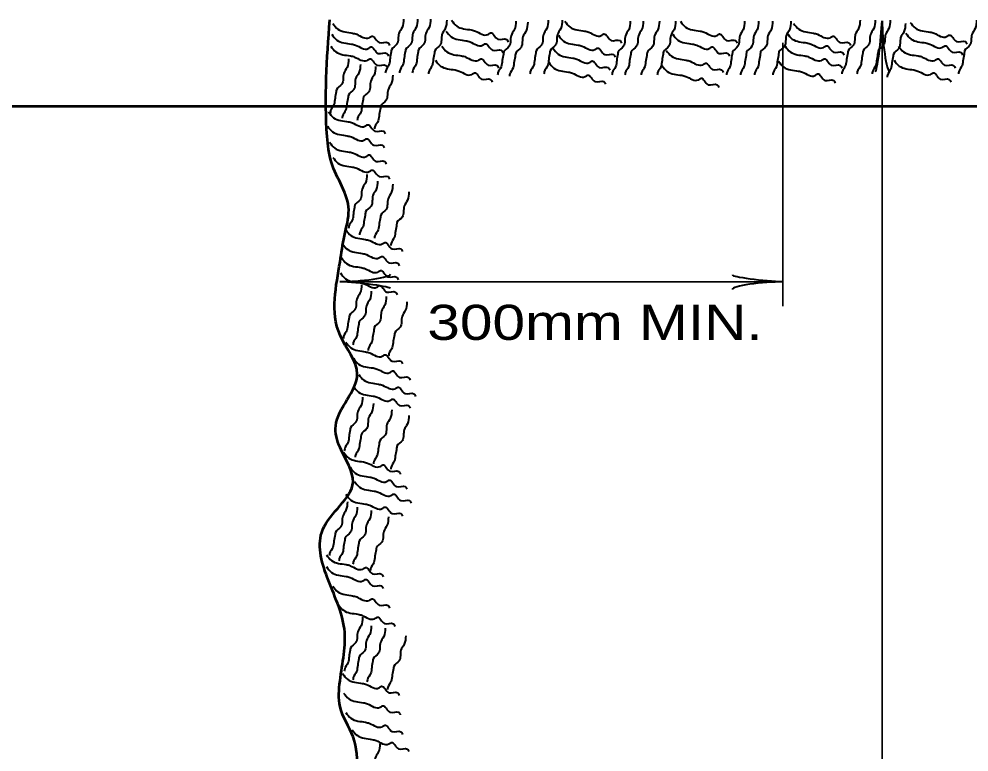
# Model space of a CAD drawing. Extents: x -617 to 238, y 23 to 567.
# Drawn here: x -228.6 to -163.5, y 332.5 to 382.7 of the extents above; entities that cross this region are included whole.
import ezdxf
from ezdxf.enums import TextEntityAlignment as Align

# ---------------------------------------------------------------- set-up
doc = ezdxf.new("R2010")
doc.units = 0
doc.header["$LTSCALE"] = 0.96
doc.layers.add('1', color=7, linetype='Continuous', lineweight=40)

msp = doc.modelspace()

# ---------------------------------------------------------------- linework, layer by layer
at = {"layer": '1', "lineweight": 35}
for p, q in [((-169.4809, 269.7739), (-169.4809, 382.5379)), ((-176.2772, 381.0289), (-176.2772, 363.0289)), ((-176.2772, 364.6978), (-206.5827, 364.6978))]:
    msp.add_line(p, q, dxfattribs=at)
at = {"layer": '1', "lineweight": 53}
msp.add_line((-325.834, 376.7054), (-133.834, 376.7054), dxfattribs=at)
at = {"layer": '1'}
for centre, major_axis, ratio, start_param, end_param in [((-169.7348, 381.1933), (-0.2108, -2.1077), 0.07063, 6.2823074, 8.5597026), ((-169.7348, 381.1933), (-0.2108, -2.1077), 0.07063, 6.2823074, 8.5597026), ((-169.1493, 381.2285), (-0.1874, 2.1428), 0.122415, 0.8963533, 3.1415927), ((-169.1493, 381.2285), (-0.1874, 2.1428), 0.122415, 0.8963533, 3.1415927), ((-205.2733, 365.0294), (-2.1428, -0.1874), 0.122415, 0.8963533, 3.1415927), ((-205.2733, 365.0294), (-2.1428, -0.1874), 0.122415, 0.8963533, 3.1415927), ((-177.6218, 364.9517), (2.1077, -0.2108), 0.07063, 3.1407148, 5.41811), ((-205.2381, 364.4439), (2.1077, -0.2108), 0.07063, 6.2823074, 8.5597026), ((-205.2381, 364.4439), (2.1077, -0.2108), 0.07063, 6.2823074, 8.5597026), ((-177.5866, 364.3662), (2.1428, 0.1874), 0.122415, 0.8963533, 3.1415927)]:
    msp.add_ellipse(centre, major_axis=major_axis, ratio=ratio, start_param=start_param, end_param=end_param, dxfattribs=at)
at = {"layer": '1', "lineweight": 53}
msp.add_spline([(-255.291, 382.6114), (-255.9281, 375.2243), (-254.7461, 372.2695), (-255.9281, 369.6102), (-255.0416, 367.2463), (-255.9281, 363.9961), (-254.7461, 361.9277), (-254.4506, 359.2684), (-254.7461, 355.1316), (-255.0416, 353.0633), (-256.2235, 351.5858), (-256.519, 350.6994), (-255.9281, 349.222), (-255.6326, 347.4491), (-255.3371, 345.3807), (-255.0416, 343.3124), (-255.0416, 340.9485), (-253.8597, 337.6982), (-254.1552, 335.6299), (-254.7461, 334.4479), (-254.7461, 331.1977), (-254.4506, 327.3564), (-254.7461, 325.879), (-254.7461, 322.6287), (-255.3371, 318.492), (-255.3371, 315.5372), (-256.519, 311.6959), (-255.6326, 309.6275), (-255.9281, 306.9682), (-256.2235, 303.7179), (-255.9281, 301.6495), (-255.6326, 298.1038), (-255.3371, 296.0354), (-255.6326, 293.6716), (-255.6326, 289.8303), (-254.7461, 288.9439), (-255.3371, 284.2162), (-255.3371, 281.5568), (-255.0416, 279.7839), (-255.6326, 276.2382), (-255.0416, 274.7608), (-255.6326, 272.1014), (-255.0416, 270.9195), (-252.6778, 268.5557), (-250.6094, 269.1466), (-248.541, 270.624), (-246.7681, 269.1466), (-244.9953, 268.8511), (-241.154, 268.8511), (-237.3127, 270.3286), (-236.1308, 269.4421), (-231.1076, 269.4421), (-226.6754, 270.0331), (-224.3116, 269.4421), (-219.2884, 270.0331), (-217.5155, 269.7376), (-212.1969, 270.0331), (-211.6059, 269.1466), (-208.0601, 269.7376), (-205.4008, 273.2834), (-205.6963, 275.3517), (-205.9918, 276.5337), (-207.7646, 282.1478), (-205.4008, 285.9891), (-206.8782, 289.2393), (-206.8782, 290.4213), (-205.6963, 292.4896), (-206.2872, 295.7399), (-205.4008, 297.2173), (-204.2189, 300.1721), (-205.9918, 305.1953), (-205.9918, 306.9682), (-205.6963, 309.0366), (-206.5827, 311.6959), (-206.2872, 313.4688), (-206.5827, 316.7191), (-207.7646, 320.8558), (-205.9918, 324.1061), (-205.6963, 326.7654), (-205.4008, 331.1977), (-205.6963, 333.5615), (-206.5827, 335.6299), (-206.5827, 337.4028), (-206.2872, 340.9485), (-207.4692, 344.4943), (-207.7646, 347.7446), (-205.6963, 350.9949), (-206.5827, 353.3587), (-206.8782, 354.8361), (-205.4008, 358.3819), (-206.5827, 361.0412), (-206.5827, 366.0644), (-206.2872, 367.8373), (-205.9918, 369.6102), (-207.1737, 372.8605), (-207.4692, 374.6334), (-207.291, 382.6114)], degree=3, dxfattribs=at)
at = {"layer": '1'}
for points in [[(-207.0771, 382.3659), (-206.7256, 381.9656), (-205.7266, 381.698), (-205.4412, 381.6216), (-204.585, 381.3921), (-204.404, 381.4966), (-203.9095, 381.0583), (-203.3006, 381.0479), (-203.1961, 380.8671)], [(-202.2362, 382.6687), (-202.3388, 382.0868), (-202.5612, 381.676), (-202.6895, 380.9484), (-203.0576, 380.5633), (-203.0831, 380.4179), (-203.1601, 379.9813), (-203.237, 379.5448), (-203.4596, 379.1341), (-203.4853, 378.9885)], [(-201.2759, 382.6687), (-201.3785, 382.0868), (-201.6009, 381.676), (-201.7292, 380.9484), (-202.0973, 380.5633), (-202.1228, 380.4179), (-202.1998, 379.9813), (-202.2767, 379.5448), (-202.4993, 379.1341), (-202.525, 378.9885)], [(-200.3895, 382.6687), (-200.4921, 382.0868), (-200.7145, 381.676), (-200.8428, 380.9484), (-201.2109, 380.5633), (-201.2364, 380.4179), (-201.3134, 379.9813), (-201.3903, 379.5448), (-201.6129, 379.1341), (-201.6386, 378.9885)], [(-199.2814, 382.5948), (-199.384, 382.0129), (-199.6064, 381.6021), (-199.7347, 380.8745), (-200.1028, 380.4894), (-200.1283, 380.344), (-200.2053, 379.9074), (-200.2822, 379.4709), (-200.5048, 379.0602), (-200.5305, 378.9146)], [(-198.9514, 382.5875), (-198.5999, 382.1872), (-197.6009, 381.9196), (-197.3155, 381.8432), (-196.4593, 381.6137), (-196.2783, 381.7182), (-195.7838, 381.2799), (-195.1749, 381.2695), (-195.0704, 381.0887)], [(-194.5537, 382.5209), (-194.6563, 381.939), (-194.8787, 381.5282), (-195.007, 380.8006), (-195.3751, 380.4155), (-195.4006, 380.2701), (-195.4776, 379.8335), (-195.5545, 379.397), (-195.7771, 378.9863), (-195.8028, 378.8407)], [(-193.7411, 382.4471), (-193.8437, 381.8652), (-194.0661, 381.4544), (-194.1944, 380.7268), (-194.5625, 380.3417), (-194.588, 380.1963), (-194.665, 379.7597), (-194.7419, 379.3232), (-194.9645, 378.9125), (-194.9902, 378.7669)], [(-192.3376, 382.5948), (-192.4402, 382.0129), (-192.6626, 381.6021), (-192.7909, 380.8745), (-193.159, 380.4894), (-193.1845, 380.344), (-193.2615, 379.9074), (-193.3384, 379.4709), (-193.561, 379.0602), (-193.5867, 378.9146)], [(-191.3772, 382.5948), (-191.4798, 382.0129), (-191.7022, 381.6021), (-191.8305, 380.8745), (-192.1986, 380.4894), (-192.2241, 380.344), (-192.3011, 379.9074), (-192.378, 379.4709), (-192.6006, 379.0602), (-192.6263, 378.9146)], [(-191.1949, 382.5137), (-190.8434, 382.1134), (-189.8444, 381.8458), (-189.559, 381.7694), (-188.7028, 381.5399), (-188.5218, 381.6444), (-188.0273, 381.2061), (-187.4184, 381.1957), (-187.3139, 381.0149)], [(-186.7234, 382.5209), (-186.826, 381.939), (-187.0484, 381.5282), (-187.1767, 380.8006), (-187.5448, 380.4155), (-187.5703, 380.2701), (-187.6473, 379.8335), (-187.7242, 379.397), (-187.9468, 378.9863), (-187.9725, 378.8407)], [(-185.837, 382.5209), (-185.9396, 381.939), (-186.162, 381.5282), (-186.2903, 380.8006), (-186.6584, 380.4155), (-186.6839, 380.2701), (-186.7609, 379.8335), (-186.8378, 379.397), (-187.0604, 378.9863), (-187.0861, 378.8407)], [(-184.7289, 382.5209), (-184.8315, 381.939), (-185.0539, 381.5282), (-185.1822, 380.8006), (-185.5503, 380.4155), (-185.5758, 380.2701), (-185.6528, 379.8335), (-185.7297, 379.397), (-185.9523, 378.9863), (-185.978, 378.8407)], [(-183.6209, 382.5209), (-183.7235, 381.939), (-183.9459, 381.5282), (-184.0742, 380.8006), (-184.4423, 380.4155), (-184.4678, 380.2701), (-184.5448, 379.8335), (-184.6217, 379.397), (-184.8443, 378.9863), (-184.87, 378.8407)], [(-183.2908, 382.5137), (-182.9393, 382.1134), (-181.9403, 381.8458), (-181.6549, 381.7694), (-180.7987, 381.5399), (-180.6177, 381.6444), (-180.1232, 381.2061), (-179.5143, 381.1957), (-179.4098, 381.0149)], [(-178.8932, 382.521), (-178.9958, 381.9391), (-179.2182, 381.5283), (-179.3465, 380.8007), (-179.7146, 380.4156), (-179.7401, 380.2702), (-179.8171, 379.8336), (-179.894, 379.3971), (-180.1166, 378.9864), (-180.1423, 378.8408)], [(-177.9329, 382.521), (-178.0355, 381.9391), (-178.2579, 381.5283), (-178.3862, 380.8007), (-178.7543, 380.4156), (-178.7798, 380.2702), (-178.8568, 379.8336), (-178.9337, 379.3971), (-179.1563, 378.9864), (-179.182, 378.8408)], [(-176.9726, 382.521), (-177.0752, 381.9391), (-177.2976, 381.5283), (-177.4259, 380.8007), (-177.794, 380.4156), (-177.8195, 380.2702), (-177.8965, 379.8336), (-177.9734, 379.3971), (-178.196, 378.9864), (-178.2217, 378.8408)], [(-175.7168, 382.521), (-175.8194, 381.9391), (-176.0418, 381.5283), (-176.1701, 380.8007), (-176.5382, 380.4156), (-176.5637, 380.2702), (-176.6407, 379.8336), (-176.7176, 379.3971), (-176.9402, 378.9864), (-176.9659, 378.8408)], [(-175.5345, 382.366), (-175.183, 381.9657), (-174.184, 381.6981), (-173.8986, 381.6217), (-173.0424, 381.3922), (-172.8614, 381.4967), (-172.3669, 381.0584), (-171.758, 381.048), (-171.6535, 380.8672)], [(-170.9891, 382.5948), (-171.0917, 382.0129), (-171.3141, 381.6021), (-171.4424, 380.8745), (-171.8105, 380.4894), (-171.836, 380.344), (-171.913, 379.9074), (-171.9899, 379.4709), (-172.2125, 379.0602), (-172.2382, 378.9146)], [(-169.9549, 382.5948), (-170.0575, 382.0129), (-170.2799, 381.6021), (-170.4082, 380.8745), (-170.7763, 380.4894), (-170.8018, 380.344), (-170.8788, 379.9074), (-170.9557, 379.4709), (-171.1783, 379.0602), (-171.204, 378.9146)], [(-168.9207, 382.5948), (-169.0233, 382.0129), (-169.2457, 381.6021), (-169.374, 380.8745), (-169.7421, 380.4894), (-169.7676, 380.344), (-169.8446, 379.9074), (-169.9215, 379.4709), (-170.1441, 379.0602), (-170.1698, 378.9146)], [(-167.8865, 382.3732), (-167.9891, 381.7913), (-168.2115, 381.3805), (-168.3398, 380.6529), (-168.7079, 380.2678), (-168.7334, 380.1224), (-168.8104, 379.6858), (-168.8873, 379.2493), (-169.1099, 378.8386), (-169.1356, 378.693)], [(-167.5565, 382.4397), (-167.205, 382.0394), (-166.206, 381.7718), (-165.9206, 381.6954), (-165.0644, 381.4659), (-164.8834, 381.5704), (-164.3889, 381.1321), (-163.78, 381.1217), (-163.6755, 380.9409)], [(-163.0111, 382.5948), (-163.1137, 382.0129), (-163.3361, 381.6021), (-163.4644, 380.8745), (-163.8325, 380.4894), (-163.858, 380.344), (-163.935, 379.9074), (-164.0119, 379.4709), (-164.2345, 379.0602), (-164.2602, 378.9146)], [(-199.3208, 381.8488), (-198.9693, 381.4485), (-197.9703, 381.1809), (-197.6849, 381.1045), (-196.8287, 380.875), (-196.6477, 380.9795), (-196.1532, 380.5412), (-195.5443, 380.5308), (-195.4398, 380.35)], [(-207.151, 381.6272), (-206.7995, 381.2269), (-205.8005, 380.9593), (-205.5151, 380.8829), (-204.6589, 380.6534), (-204.4779, 380.7579), (-203.9834, 380.3196), (-203.3745, 380.3092), (-203.27, 380.1284)], [(-191.6382, 381.5534), (-191.2867, 381.1531), (-190.2877, 380.8855), (-190.0023, 380.8091), (-189.1461, 380.5796), (-188.9651, 380.6841), (-188.4706, 380.2458), (-187.8617, 380.2354), (-187.7572, 380.0546)], [(-183.8079, 381.6272), (-183.4564, 381.2269), (-182.4574, 380.9593), (-182.172, 380.8829), (-181.3158, 380.6534), (-181.1348, 380.7579), (-180.6403, 380.3196), (-180.0314, 380.3092), (-179.9269, 380.1284)], [(-175.9777, 381.7011), (-175.6262, 381.3008), (-174.6272, 381.0332), (-174.3418, 380.9568), (-173.4856, 380.7273), (-173.3046, 380.8318), (-172.8101, 380.3935), (-172.2012, 380.3831), (-172.0967, 380.2023)], [(-167.8519, 381.701), (-167.5004, 381.3007), (-166.5014, 381.0331), (-166.216, 380.9567), (-165.3598, 380.7272), (-165.1788, 380.8317), (-164.6843, 380.3934), (-164.0754, 380.383), (-163.9709, 380.2022)], [(-207.2248, 380.8146), (-206.8733, 380.4143), (-205.8743, 380.1467), (-205.5889, 380.0703), (-204.7327, 379.8408), (-204.5517, 379.9453), (-204.0572, 379.507), (-203.4483, 379.4966), (-203.3438, 379.3158)], [(-199.6162, 380.8146), (-199.2647, 380.4143), (-198.2657, 380.1467), (-197.9803, 380.0703), (-197.1241, 379.8408), (-196.9431, 379.9453), (-196.4486, 379.507), (-195.8397, 379.4966), (-195.7352, 379.3158)], [(-192.0075, 380.6669), (-191.656, 380.2666), (-190.657, 379.999), (-190.3716, 379.9226), (-189.5154, 379.6931), (-189.3344, 379.7976), (-188.8399, 379.3593), (-188.231, 379.3489), (-188.1265, 379.1681)], [(-184.2511, 380.5192), (-183.8996, 380.1189), (-182.9006, 379.8513), (-182.6152, 379.7749), (-181.759, 379.5454), (-181.578, 379.6499), (-181.0835, 379.2116), (-180.4746, 379.2012), (-180.3701, 379.0204)], [(-176.1254, 380.8147), (-175.7739, 380.4144), (-174.7749, 380.1468), (-174.4895, 380.0704), (-173.6333, 379.8409), (-173.4523, 379.9454), (-172.9578, 379.5071), (-172.3489, 379.4967), (-172.2444, 379.3159)], [(-168.369, 380.8146), (-168.0175, 380.4143), (-167.0185, 380.1467), (-166.7331, 380.0703), (-165.8769, 379.8408), (-165.6959, 379.9453), (-165.2014, 379.507), (-164.5925, 379.4966), (-164.488, 379.3158)], [(-206.0036, 379.9355), (-206.1062, 379.3536), (-206.3286, 378.9428), (-206.4569, 378.2152), (-206.825, 377.8301), (-206.8505, 377.6847), (-206.9275, 377.2481), (-207.0044, 376.8116), (-207.227, 376.4009), (-207.2527, 376.2553)], [(-200.0595, 379.8543), (-199.708, 379.454), (-198.709, 379.1864), (-198.4236, 379.11), (-197.5674, 378.8805), (-197.3864, 378.985), (-196.8919, 378.5467), (-196.283, 378.5363), (-196.1785, 378.3555)], [(-176.5687, 379.7805), (-176.2172, 379.3802), (-175.2182, 379.1126), (-174.9328, 379.0362), (-174.0766, 378.8067), (-173.8956, 378.9112), (-173.4011, 378.4729), (-172.7922, 378.4625), (-172.6877, 378.2817)], [(-168.6645, 379.8543), (-168.313, 379.454), (-167.314, 379.1864), (-167.0286, 379.11), (-166.1724, 378.8805), (-165.9914, 378.985), (-165.4969, 378.5467), (-164.888, 378.5363), (-164.7835, 378.3555)], [(-205.1911, 379.5661), (-205.2937, 378.9842), (-205.5161, 378.5734), (-205.6444, 377.8458), (-206.0125, 377.4607), (-206.038, 377.3153), (-206.115, 376.8787), (-206.1919, 376.4422), (-206.4145, 376.0315), (-206.4402, 375.8859)], [(-204.1569, 379.4184), (-204.2595, 378.8365), (-204.4819, 378.4257), (-204.6102, 377.6981), (-204.9783, 377.313), (-205.0038, 377.1676), (-205.0808, 376.731), (-205.1577, 376.2945), (-205.3803, 375.8838), (-205.406, 375.7382)], [(-192.303, 379.7066), (-191.9515, 379.3063), (-190.9525, 379.0387), (-190.6671, 378.9623), (-189.8109, 378.7328), (-189.6299, 378.8373), (-189.1354, 378.399), (-188.5265, 378.3886), (-188.422, 378.2078)], [(-184.5466, 379.485), (-184.1951, 379.0847), (-183.1961, 378.8171), (-182.9107, 378.7407), (-182.0545, 378.5112), (-181.8735, 378.6157), (-181.379, 378.1774), (-180.7701, 378.167), (-180.6656, 377.9862)], [(-202.975, 378.8274), (-203.0776, 378.2455), (-203.3, 377.8347), (-203.4283, 377.1071), (-203.7964, 376.722), (-203.8219, 376.5766), (-203.8989, 376.14), (-203.9758, 375.7035), (-204.1984, 375.2928), (-204.2241, 375.1472)], [(-207.3726, 376.3086), (-207.0211, 375.9083), (-206.0221, 375.6407), (-205.7367, 375.5643), (-204.8805, 375.3348), (-204.6995, 375.4393), (-204.205, 375.001), (-203.5961, 374.9906), (-203.4916, 374.8098)], [(-207.4464, 375.3483), (-207.0949, 374.948), (-206.0959, 374.6804), (-205.8105, 374.604), (-204.9543, 374.3745), (-204.7733, 374.479), (-204.2788, 374.0407), (-203.6699, 374.0303), (-203.5654, 373.8495)], [(-207.2987, 374.2402), (-206.9472, 373.8399), (-205.9482, 373.5723), (-205.6628, 373.4959), (-204.8066, 373.2664), (-204.6256, 373.3709), (-204.1311, 372.9326), (-203.5222, 372.9222), (-203.4177, 372.7414)], [(-207.0771, 373.206), (-206.7256, 372.8057), (-205.7266, 372.5381), (-205.4412, 372.4617), (-204.585, 372.2322), (-204.404, 372.3367), (-203.9095, 371.8984), (-203.3006, 371.888), (-203.1961, 371.7072)], [(-204.7479, 372.0313), (-204.8505, 371.4494), (-205.0729, 371.0386), (-205.2012, 370.311), (-205.5693, 369.9259), (-205.5948, 369.7805), (-205.6718, 369.3439), (-205.7487, 368.9074), (-205.9713, 368.4967), (-205.997, 368.3511)], [(-204.0091, 371.5881), (-204.1117, 371.0062), (-204.3341, 370.5954), (-204.4624, 369.8678), (-204.8305, 369.4827), (-204.856, 369.3373), (-204.933, 368.9007), (-205.0099, 368.4642), (-205.2325, 368.0535), (-205.2582, 367.9079)], [(-202.975, 371.3665), (-203.0776, 370.7846), (-203.3, 370.3738), (-203.4283, 369.6462), (-203.7964, 369.2611), (-203.8219, 369.1157), (-203.8989, 368.6791), (-203.9758, 368.2426), (-204.1984, 367.8319), (-204.2241, 367.6863)], [(-201.8669, 370.8494), (-201.9695, 370.2675), (-202.1919, 369.8567), (-202.3202, 369.1291), (-202.6883, 368.744), (-202.7138, 368.5986), (-202.7908, 368.162), (-202.8677, 367.7255), (-203.0903, 367.3148), (-203.116, 367.1692)], [(-206.1907, 368.2567), (-205.8392, 367.8564), (-204.8402, 367.5888), (-204.5548, 367.5124), (-203.6986, 367.2829), (-203.5176, 367.3874), (-203.0231, 366.9491), (-202.4142, 366.9387), (-202.3097, 366.7579)], [(-206.4123, 367.2963), (-206.0608, 366.896), (-205.0618, 366.6284), (-204.7764, 366.552), (-203.9202, 366.3225), (-203.7392, 366.427), (-203.2447, 365.9887), (-202.6358, 365.9783), (-202.5313, 365.7975)], [(-206.4862, 366.336), (-206.1347, 365.9357), (-205.1357, 365.6681), (-204.8503, 365.5917), (-203.9941, 365.3622), (-203.8131, 365.4667), (-203.3186, 365.0284), (-202.7097, 365.018), (-202.6052, 364.8372)], [(-206.56, 365.3018), (-206.2085, 364.9015), (-205.2095, 364.6339), (-204.9241, 364.5575), (-204.0679, 364.328), (-203.8869, 364.4325), (-203.3924, 363.9942), (-202.7835, 363.9838), (-202.679, 363.803)], [(-205.1172, 364.4966), (-205.2198, 363.9147), (-205.4422, 363.5039), (-205.5705, 362.7763), (-205.9386, 362.3912), (-205.9641, 362.2458), (-206.0411, 361.8092), (-206.118, 361.3727), (-206.3406, 360.962), (-206.3663, 360.8164)], [(-204.4524, 364.0534), (-204.555, 363.4715), (-204.7774, 363.0607), (-204.9057, 362.3331), (-205.2738, 361.948), (-205.2993, 361.8026), (-205.3763, 361.366), (-205.4532, 360.9295), (-205.6758, 360.5188), (-205.7015, 360.3732)], [(-203.4182, 363.684), (-203.5208, 363.1021), (-203.7432, 362.6913), (-203.8715, 361.9637), (-204.2396, 361.5786), (-204.2651, 361.4332), (-204.3421, 360.9966), (-204.419, 360.5601), (-204.6416, 360.1494), (-204.6673, 360.0038)], [(-202.0146, 363.3147), (-202.1172, 362.7328), (-202.3396, 362.322), (-202.4679, 361.5944), (-202.836, 361.2093), (-202.8615, 361.0639), (-202.9385, 360.6273), (-203.0154, 360.1908), (-203.238, 359.7801), (-203.2637, 359.6345)], [(-206.1906, 360.5741), (-205.8391, 360.1738), (-204.8401, 359.9062), (-204.5547, 359.8298), (-203.6985, 359.6003), (-203.5175, 359.7048), (-203.023, 359.2665), (-202.4141, 359.2561), (-202.3096, 359.0753)], [(-205.6735, 359.4661), (-205.322, 359.0658), (-204.323, 358.7982), (-204.0376, 358.7218), (-203.1814, 358.4923), (-203.0004, 358.5968), (-202.5059, 358.1585), (-201.897, 358.1481), (-201.7925, 357.9673)], [(-205.3042, 358.358), (-204.9527, 357.9577), (-203.9537, 357.6901), (-203.6683, 357.6137), (-202.8121, 357.3842), (-202.6311, 357.4887), (-202.1366, 357.0504), (-201.5277, 357.04), (-201.4232, 356.8592)], [(-205.6735, 357.5454), (-205.322, 357.1451), (-204.323, 356.8775), (-204.0376, 356.8011), (-203.1814, 356.5716), (-203.0004, 356.6761), (-202.5059, 356.2378), (-201.897, 356.2274), (-201.7925, 356.0466)], [(-205.0433, 356.814), (-205.1459, 356.2321), (-205.3683, 355.8213), (-205.4966, 355.0937), (-205.8647, 354.7086), (-205.8902, 354.5632), (-205.9672, 354.1266), (-206.0441, 353.6901), (-206.2667, 353.2794), (-206.2924, 353.1338)], [(-204.3046, 356.3708), (-204.4072, 355.7889), (-204.6296, 355.3781), (-204.7579, 354.6505), (-205.126, 354.2654), (-205.1515, 354.12), (-205.2285, 353.6834), (-205.3054, 353.2469), (-205.528, 352.8362), (-205.5537, 352.6906)], [(-203.0488, 355.9276), (-203.1514, 355.3457), (-203.3738, 354.9349), (-203.5021, 354.2073), (-203.8702, 353.8222), (-203.8957, 353.6768), (-203.9727, 353.2402), (-204.0496, 352.8037), (-204.2722, 352.393), (-204.2979, 352.2474)], [(-201.8669, 355.5582), (-201.9695, 354.9763), (-202.1919, 354.5655), (-202.3202, 353.8379), (-202.6883, 353.4528), (-202.7138, 353.3074), (-202.7908, 352.8708), (-202.8677, 352.4343), (-203.0903, 352.0236), (-203.116, 351.878)], [(-206.3384, 353.0394), (-205.9869, 352.6391), (-204.9879, 352.3715), (-204.7025, 352.2951), (-203.8463, 352.0656), (-203.6653, 352.1701), (-203.1708, 351.7318), (-202.5619, 351.7214), (-202.4574, 351.5406)], [(-205.8951, 352.0052), (-205.5436, 351.6049), (-204.5446, 351.3373), (-204.2592, 351.2609), (-203.403, 351.0314), (-203.222, 351.1359), (-202.7275, 350.6976), (-202.1186, 350.6872), (-202.0141, 350.5064)], [(-205.5997, 351.0449), (-205.2482, 350.6446), (-204.2492, 350.377), (-203.9638, 350.3006), (-203.1076, 350.0711), (-202.9266, 350.1756), (-202.4321, 349.7373), (-201.8232, 349.7269), (-201.7187, 349.5461)], [(-206.1906, 350.1585), (-205.8391, 349.7582), (-204.8401, 349.4906), (-204.5547, 349.4142), (-203.6985, 349.1847), (-203.5175, 349.2892), (-203.023, 348.8509), (-202.4141, 348.8405), (-202.3096, 348.6597)], [(-206.0775, 349.6486), (-206.1801, 349.0667), (-206.4025, 348.6559), (-206.5308, 347.9283), (-206.8989, 347.5432), (-206.9244, 347.3978), (-207.0014, 346.9612), (-207.0783, 346.5247), (-207.3009, 346.114), (-207.3266, 345.9684)], [(-205.4126, 349.2792), (-205.5152, 348.6973), (-205.7376, 348.2865), (-205.8659, 347.5589), (-206.234, 347.1738), (-206.2595, 347.0284), (-206.3365, 346.5918), (-206.4134, 346.1553), (-206.636, 345.7446), (-206.6617, 345.599)], [(-204.4523, 349.0576), (-204.5549, 348.4757), (-204.7773, 348.0649), (-204.9056, 347.3373), (-205.2737, 346.9522), (-205.2992, 346.8068), (-205.3762, 346.3702), (-205.4531, 345.9337), (-205.6757, 345.523), (-205.7014, 345.3774)], [(-203.2704, 348.6144), (-203.373, 348.0325), (-203.5954, 347.6217), (-203.7237, 346.8941), (-204.0918, 346.509), (-204.1173, 346.3636), (-204.1943, 345.927), (-204.2712, 345.4905), (-204.4938, 345.0798), (-204.5195, 344.9342)], [(-207.5203, 346.0217), (-207.1688, 345.6214), (-206.1698, 345.3538), (-205.8844, 345.2774), (-205.0282, 345.0479), (-204.8472, 345.1524), (-204.3527, 344.7141), (-203.7438, 344.7037), (-203.6393, 344.5229)], [(-207.5203, 345.2092), (-207.1688, 344.8089), (-206.1698, 344.5413), (-205.8844, 344.4649), (-205.0282, 344.2354), (-204.8472, 344.3399), (-204.3527, 343.9016), (-203.7438, 343.8912), (-203.6393, 343.7104)], [(-207.0771, 343.8795), (-206.7256, 343.4792), (-205.7266, 343.2116), (-205.4412, 343.1352), (-204.585, 342.9057), (-204.404, 343.0102), (-203.9095, 342.5719), (-203.3006, 342.5615), (-203.1961, 342.3807)], [(-206.7078, 342.6237), (-206.3563, 342.2234), (-205.3573, 341.9558), (-205.0719, 341.8794), (-204.2157, 341.6499), (-204.0347, 341.7544), (-203.5402, 341.3161), (-202.9313, 341.3057), (-202.8268, 341.1249)], [(-205.0432, 341.7444), (-205.1458, 341.1625), (-205.3682, 340.7517), (-205.4965, 340.0241), (-205.8646, 339.639), (-205.8901, 339.4936), (-205.9671, 339.057), (-206.044, 338.6205), (-206.2666, 338.2098), (-206.2923, 338.0642)], [(-204.4523, 341.1535), (-204.5549, 340.5716), (-204.7773, 340.1608), (-204.9056, 339.4332), (-205.2737, 339.0481), (-205.2992, 338.9027), (-205.3762, 338.4661), (-205.4531, 338.0296), (-205.6757, 337.6189), (-205.7014, 337.4733)], [(-203.492, 341.0057), (-203.5946, 340.4238), (-203.817, 340.013), (-203.9453, 339.2854), (-204.3134, 338.9003), (-204.3389, 338.7549), (-204.4159, 338.3183), (-204.4928, 337.8818), (-204.7154, 337.4711), (-204.7411, 337.3255)], [(-202.0884, 340.4886), (-202.191, 339.9067), (-202.4134, 339.4959), (-202.5417, 338.7683), (-202.9098, 338.3832), (-202.9353, 338.2378), (-203.0123, 337.8012), (-203.0892, 337.3647), (-203.3118, 336.954), (-203.3375, 336.8084)], [(-206.4123, 337.896), (-206.0608, 337.4957), (-205.0618, 337.2281), (-204.7764, 337.1517), (-203.9202, 336.9222), (-203.7392, 337.0267), (-203.2447, 336.5884), (-202.6358, 336.578), (-202.5313, 336.3972)], [(-206.3384, 336.5663), (-205.9869, 336.166), (-204.9879, 335.8984), (-204.7025, 335.822), (-203.8463, 335.5925), (-203.6653, 335.697), (-203.1708, 335.2587), (-202.5619, 335.2483), (-202.4574, 335.0675)], [(-206.1906, 335.2366), (-205.8391, 334.8363), (-204.8401, 334.5687), (-204.5547, 334.4923), (-203.6985, 334.2628), (-203.5175, 334.3673), (-203.023, 333.929), (-202.4141, 333.9186), (-202.3096, 333.7378)], [(-205.7474, 334.0547), (-205.3959, 333.6544), (-204.3969, 333.3868), (-204.1115, 333.3104), (-203.2553, 333.0809), (-203.0743, 333.1854), (-202.5798, 332.7471), (-201.9709, 332.7367), (-201.8664, 332.5559)], [(-203.8613, 333.1016), (-203.9639, 332.5197), (-204.1863, 332.1089), (-204.3146, 331.3813), (-204.6827, 330.9962), (-204.7082, 330.8508), (-204.7852, 330.4142), (-204.8621, 329.9777), (-205.0847, 329.567), (-205.1104, 329.4214)]]:
    msp.add_spline(points, degree=3, dxfattribs=at)

# ---------------------------------------------------------------- texts
at = {"layer": '1', "width": 1.25}
msp.add_text('300mm MIN.', height=2.4, dxfattribs=at).set_placement((-189.1325, 360.7206), align=Align.CENTER)

doc.saveas('drawing.dxf')
